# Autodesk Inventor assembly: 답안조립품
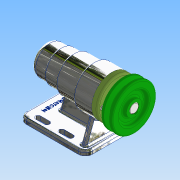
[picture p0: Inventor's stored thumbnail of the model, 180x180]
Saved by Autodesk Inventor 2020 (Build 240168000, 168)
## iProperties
Created: 2021-10
Part Number: 답안조립품
Document SubType Name: Assembly
Designer: user
Author: user
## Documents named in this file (12)
- C:\Users\user\Desktop\711007V1002\답안조립품.iam
- C:\Users\user\Desktop\711007V1002\V벨트풀리.ipt
- C:\Users\user\Desktop\711007V1002\멈춤나사 M3.ipt
- C:\Users\user\Desktop\711007V1002\베어링 6004.ipt
- C:\Users\user\Desktop\711007V1002\베어링 51202.ipt
- C:\Users\user\Desktop\711007V1002\본체.ipt
- C:\Users\user\Desktop\711007V1002\볼트 M4.ipt
- C:\Users\user\Desktop\711007V1002\어댑터슬리브.ipt
- C:\Users\user\Desktop\711007V1002\오일 실 20x35x7.ipt
- C:\Users\user\Desktop\711007V1002\축.ipt
- C:\Users\user\Desktop\711007V1002\커버.ipt
- C:\Users\user\Desktop\711007V1002\키 5x5.ipt
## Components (1 placed, 1 different names)
1. V벨트풀리:1
